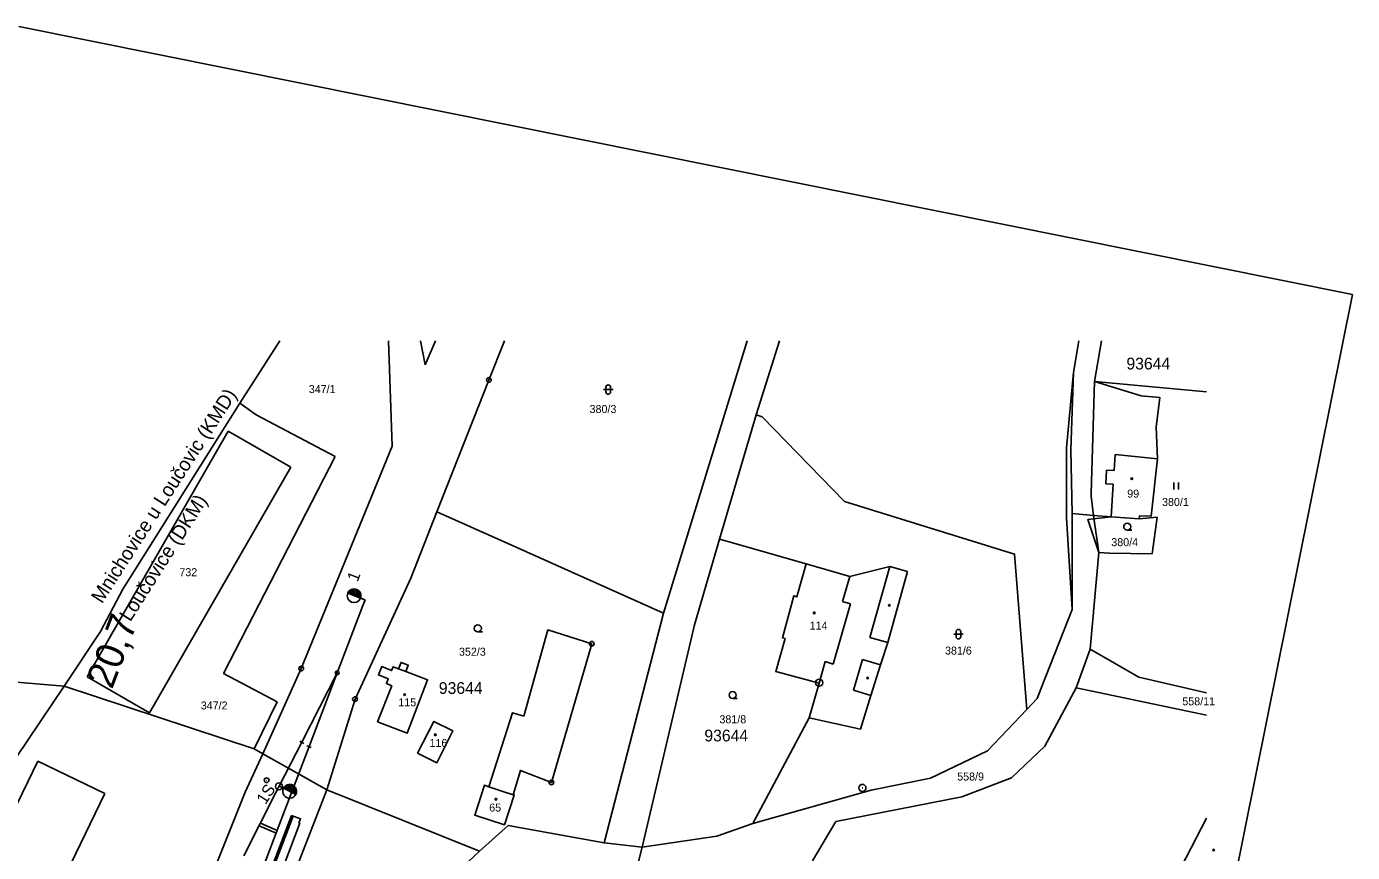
# Model space of a CAD drawing. Extents: x -778045 to -777594, y -1202682 to -1202213.
# Drawn here: x -777875.5 to -777593.8, y -1202388.9 to -1202213.3 of the extents above; entities that cross this region are included whole.
import ezdxf

# ---------------------------------------------------------------- set-up
doc = ezdxf.new("R2010")
doc.units = 0
for name, color, linetype in [('BPEJ', 7, 'Continuous'), ('GD_Starý stav', 7, 'Continuous'), ('Katastr_HRANICE DRÁHY', 7, 'Continuous'), ('Katastr_Hranice katastrální', 7, 'Continuous'), ('Katastr_Hranice parcel', 7, 'Continuous'), ('Katastr_Parcelní čísla', 7, 'Continuous'), ('Katastr_Slučkované čáry', 7, 'Continuous'), ('Katastr_Značky kultur', 7, 'Continuous'), ('Vrstva 7', 7, 'Continuous')]:
    doc.layers.add(name, color=color, linetype=linetype)

msp = doc.modelspace()

# ---------------------------------------------------------------- linework, layer by layer
at = {"layer": 'BPEJ'}
for points in [[(-777715.51, -1202280.12), (-777720.45, -1202295.86), (-777719.2, -1202296.33), (-777701.71, -1202314.27), (-777665.58, -1202325.46), (-777663.01, -1202358.54), (-777660.78, -1202356.18), (-777659.91, -1202353.96), (-777653.34, -1202337.23), (-777654.57, -1202317.8), (-777654.55, -1202302.89), (-777653.05, -1202286.88), (-777651.96, -1202280.12)], [(-777647.08, -1202280.12), (-777648.6, -1202288.78), (-777638.72, -1202291.84), (-777634.69, -1202292.2), (-777635.48, -1202298.47), (-777635.2, -1202305.22), (-777636.54, -1202317.41), (-777639.06, -1202317.35), (-777639.1, -1202318), (-777645.06, -1202317.53), (-777650.01, -1202318.12), (-777647.71, -1202325.12), (-777649.49, -1202345.7), (-777639.21, -1202351.67), (-777624.79, -1202354.99)], [(-777788.3, -1202316.49), (-777774.01, -1202322.88), (-777740.14, -1202338.03), (-777752.8, -1202386.89), (-777773.14, -1202383.15), (-777779.27, -1202388.61), (-777811.7, -1202375.6), (-777805.7, -1202356.3), (-777793.87, -1202330.63), (-777788.3, -1202316.49)], [(-777728.24, -1202322.3), (-777726.98, -1202322.66), (-777709.85, -1202327.57), (-777711.82, -1202334.53), (-777712.49, -1202334.34), (-777714.9, -1202343.3), (-777714.35, -1202343.45), (-777716.32, -1202350.41), (-777707.07, -1202352.95), (-777709.23, -1202360.29), (-777721.22, -1202382.72), (-777728.85, -1202385.43), (-777744.73, -1202387.77), (-777733.6, -1202340.49), (-777728.24, -1202322.3)], [(-777769.85, -1202359.94), (-777764.72, -1202341.59), (-777755.42, -1202344.55), (-777763.99, -1202374), (-777770.53, -1202371.45), (-777772.08, -1202376.64), (-777771.88, -1202376.7), (-777773.95, -1202383.02), (-777780.27, -1202380.95), (-777778.2, -1202374.63), (-777777.29, -1202374.93), (-777772.26, -1202359.22), (-777769.85, -1202359.94)], [(-777796.44, -1202349.87), (-777795.91, -1202348.51), (-777794.39, -1202349.09), (-777794.91, -1202350.46), (-777790.27, -1202352.24), (-777794.6, -1202363.54), (-777800.91, -1202361.12), (-777797.88, -1202353.49), (-777799.04, -1202353.02), (-777798.64, -1202352), (-777800.73, -1202351.17), (-777800.03, -1202349.39), (-777797.93, -1202350.23), (-777797.61, -1202349.41), (-777796.44, -1202349.87)], [(-777792.39, -1202367.77), (-777788.94, -1202361.03), (-777784.91, -1202363.08), (-777788.31, -1202369.84), (-777792.39, -1202367.77)]]:
    msp.add_lwpolyline(points, dxfattribs=at)
at = {"layer": 'Defpoints'}
for q in [(-777877.12, -1202213.32), (-777676.59, -1202682.05)]:
    msp.add_line((-777593.79, -1202270.29), q, dxfattribs=at)
at = {"layer": 'GD_Starý stav'}
for p, q in [((-777806.9, -1202333.95), (-777807.1, -1202333.51)), ((-777806.41, -1202334.14), (-777806.82, -1202333.21)), ((-777805.91, -1202334.33), (-777806.5, -1202333.01)), ((-777805.41, -1202334.52), (-777806.14, -1202332.9)), ((-777804.92, -1202334.71), (-777805.74, -1202332.88)), ((-777804.49, -1202334.75), (-777805.26, -1202333.02)), ((-777804.52, -1202334.86), (-777803.56, -1202335.22)), ((-777809.48, -1202350.75), (-777816.98, -1202365.49)), ((-777816.98, -1202365.49), (-777809.48, -1202350.75)), ((-777816.54, -1202365.72), (-777817.42, -1202365.26)), ((-777816.98, -1202365.49), (-777821.8, -1202374.78)), ((-777814.99, -1202366.59), (-777815.92, -1202366.23)), ((-777822.51, -1202376.18), (-777829.29, -1202389.61)), ((-777822.51, -1202376.18), (-777829.29, -1202389.61)), ((-777821.8, -1202374.78), (-777822.51, -1202376.18)), ((-777821.8, -1202374.78), (-777822.51, -1202376.18)), ((-777820.87, -1202375.24), (-777821.8, -1202374.78)), ((-777820.66, -1202374.94), (-777820.5, -1202375.43)), ((-777820.35, -1202374.67), (-777820.02, -1202375.67)), ((-777820, -1202374.51), (-777819.54, -1202375.92)), ((-777819.63, -1202374.44), (-777819.06, -1202376.16)), ((-777819.21, -1202374.48), (-777818.58, -1202376.4)), ((-777818.74, -1202374.69), (-777818.18, -1202376.37)), ((-777826.07, -1202383.23), (-777822.47, -1202384.82)), ((-777825.8, -1202382.7), (-777822.26, -1202384.26))]:
    msp.add_line(p, q, dxfattribs=at)
for points in [[(-777804.52, -1202334.86), (-777807.26, -1202333.81)], [(-777803.56, -1202335.22), (-777804.09, -1202336.62), (-777809.48, -1202350.75), (-777815.46, -1202366.41)], [(-777815.46, -1202366.41), (-777809.48, -1202350.75), (-777804.09, -1202336.62), (-777803.56, -1202335.22)], [(-777804.52, -1202334.86), (-777804.52, -1202334.86)], [(-777865.08, -1202504.23), (-777861.67, -1202489.74), (-777857.48, -1202477.13), (-777850.38, -1202458.32), (-777840.49, -1202432.25), (-777830.62, -1202406.28), (-777821.88, -1202383.27), (-777815.46, -1202366.41)], [(-777818.26, -1202376.56), (-777820.87, -1202375.24)], [(-777818.26, -1202376.56), (-777818.26, -1202376.56)], [(-777844.11, -1202457.24), (-777847.57, -1202455.83), (-777842.63, -1202442.78), (-777837.65, -1202429.62), (-777832.66, -1202416.55), (-777826.6, -1202400.65), (-777819.16, -1202381.05)], [(-777847.25, -1202456.03), (-777842.26, -1202442.89), (-777837.28, -1202429.79), (-777832.33, -1202416.64), (-777826.31, -1202400.77), (-777818.81, -1202381.19), (-777818.81, -1202381.2)], [(-777844.11, -1202457.24), (-777839.11, -1202444.1), (-777835.76, -1202435.24), (-777834.05, -1202430.85), (-777833.28, -1202428.8), (-777831.86, -1202428.99), (-777831.3, -1202427.43), (-777832.54, -1202426.83), (-777830.84, -1202422.31), (-777831.43, -1202422.03), (-777830.16, -1202418.71), (-777829.52, -1202418.79), (-777826.31, -1202410.46), (-777827.69, -1202409.96), (-777827.2, -1202408.71), (-777825.88, -1202409.2), (-777823.46, -1202402.62), (-777824.77, -1202402.13), (-777817.44, -1202382.7), (-777817.6, -1202382.63), (-777817.25, -1202381.75), (-777819.16, -1202381.05)]]:
    msp.add_lwpolyline(points, dxfattribs=at)
for centre, radius in [((-777805.9, -1202334.33), 1.46), ((-777809.48, -1202350.75), 0.4)]:
    msp.add_circle(centre, radius, dxfattribs=at)
for centre, start, end in [((-777805.89, -1202334.34), 339.1309, 159.0918), ((-777819.57, -1202375.9), 153.2834, 333.7529), ((-777819.57, -1202375.9), 333.368, 153.3289)]:
    msp.add_arc(centre, 1.46, start, end, dxfattribs=at)
at = {"layer": 'Katastr_HRANICE DRÁHY'}
for points in [[(-777798.62, -1202280.12), (-777797.84, -1202302.55)], [(-777791.78, -1202280.12), (-777790.77, -1202285.22)], [(-777790.77, -1202285.22), (-777788.57, -1202280.12)], [(-777777.27, -1202288.47), (-777773.95, -1202280.12)], [(-777788.3, -1202316.49), (-777777.27, -1202288.47)], [(-777817.11, -1202349.82), (-777797.84, -1202302.55)], [(-777788.3, -1202316.49), (-777793.87, -1202330.63)], [(-777805.7, -1202356.3), (-777793.87, -1202330.63)], [(-777817.11, -1202349.82), (-777825.29, -1202367.91)], [(-777805.7, -1202356.3), (-777811.7, -1202375.6)], [(-777825.29, -1202367.91), (-777829.01, -1202376.12)], [(-777841.03, -1202405.98), (-777829.01, -1202376.12)], [(-777811.7, -1202375.6), (-777821.08, -1202399.82)]]:
    msp.add_lwpolyline(points, dxfattribs=at)
at = {"layer": 'Katastr_Hranice katastrální'}
for points in [[(-777830.2, -1202293.41), (-777821.68, -1202280.12)], [(-777854.99, -1202332.94), (-777830.2, -1202293.41)], [(-777859.77, -1202341.9), (-777854.99, -1202332.94)], [(-777867.47, -1202353.53), (-777859.77, -1202341.9)], [(-777906.41, -1202350.32), (-777867.47, -1202353.53)]]:
    msp.add_lwpolyline(points, dxfattribs=at)
at = {"layer": 'Katastr_Hranice parcel'}
msp.add_line((-777648.6, -1202288.78), (-777624.79, -1202291.01), dxfattribs=at)
for points in [[(-777722.39, -1202280.12), (-777740.14, -1202338.03)], [(-777715.51, -1202280.12), (-777720.45, -1202295.86)], [(-777653.05, -1202286.88), (-777651.96, -1202280.12)], [(-777648.6, -1202288.78), (-777647.08, -1202280.12)], [(-777653.05, -1202286.88), (-777653.66, -1202303.32)], [(-777648.6, -1202288.78), (-777649.33, -1202312.52)], [(-777648.6, -1202288.78), (-777638.72, -1202291.84)], [(-777638.72, -1202291.84), (-777634.69, -1202292.2)], [(-777830.2, -1202293.41), (-777826.67, -1202295.84)], [(-777634.69, -1202292.2), (-777635.48, -1202298.47)], [(-777826.67, -1202295.84), (-777809.94, -1202304.72)], [(-777728.24, -1202322.3), (-777720.45, -1202295.86)], [(-777720.45, -1202295.86), (-777719.2, -1202296.33)], [(-777701.71, -1202314.27), (-777719.2, -1202296.33)], [(-777832.67, -1202299.35), (-777862.62, -1202351.59)], [(-777819.32, -1202307.02), (-777832.67, -1202299.35)], [(-777635.48, -1202298.47), (-777635.2, -1202305.22)], [(-777653.66, -1202303.32), (-777653.34, -1202316.88)], [(-777809.94, -1202304.72), (-777833.64, -1202350.84)], [(-777635.2, -1202305.22), (-777636.54, -1202317.41)], [(-777849.34, -1202359.23), (-777819.32, -1202307.02)], [(-777665.58, -1202325.46), (-777701.71, -1202314.27)], [(-777649.33, -1202312.52), (-777649.34, -1202313.17), (-777648.79, -1202317.24)], [(-777788.3, -1202316.49), (-777774.01, -1202322.88)], [(-777653.34, -1202316.88), (-777653.34, -1202337.23)], [(-777653.34, -1202316.88), (-777648.79, -1202317.24)], [(-777648.79, -1202317.24), (-777645.06, -1202317.53)], [(-777648.79, -1202317.24), (-777647.71, -1202325.12)], [(-777639.06, -1202317.35), (-777639.1, -1202318)], [(-777636.54, -1202317.41), (-777639.06, -1202317.35)], [(-777645.06, -1202317.53), (-777639.1, -1202318)], [(-777639.1, -1202318), (-777635.26, -1202317.6)], [(-777635.26, -1202317.6), (-777636.36, -1202325.39)], [(-777774.01, -1202322.88), (-777740.14, -1202338.03)], [(-777733.6, -1202340.49), (-777728.24, -1202322.3)], [(-777728.24, -1202322.3), (-777726.98, -1202322.66)], [(-777726.98, -1202322.66), (-777709.85, -1202327.57)], [(-777665.58, -1202325.46), (-777663.01, -1202358.54)], [(-777647.71, -1202325.12), (-777649.49, -1202345.7)], [(-777645.43, -1202325.29), (-777647.71, -1202325.12)], [(-777636.36, -1202325.39), (-777645.43, -1202325.29)], [(-777709.85, -1202327.57), (-777711.82, -1202334.53)], [(-777700.6, -1202330.22), (-777709.85, -1202327.57)], [(-777700.6, -1202330.22), (-777692.1, -1202328.08)], [(-777692.1, -1202328.08), (-777688.3, -1202329.15)], [(-777688.3, -1202329.15), (-777692.54, -1202344.26)], [(-777712.49, -1202334.34), (-777714.9, -1202343.3)], [(-777711.82, -1202334.53), (-777712.49, -1202334.34)], [(-777653.34, -1202337.23), (-777659.91, -1202353.96)], [(-777752.8, -1202386.89), (-777740.14, -1202338.03)], [(-777769.85, -1202359.94), (-777764.72, -1202341.59)], [(-777755.42, -1202344.55), (-777764.72, -1202341.59)], [(-777733.6, -1202340.49), (-777744.73, -1202387.77)], [(-777755.42, -1202344.55), (-777763.99, -1202374)], [(-777714.35, -1202343.45), (-777716.32, -1202350.41)], [(-777714.9, -1202343.3), (-777714.35, -1202343.45)], [(-777694.06, -1202349.02), (-777692.54, -1202344.26)], [(-777649.49, -1202345.7), (-777652.48, -1202353.91)], [(-777649.49, -1202345.7), (-777639.21, -1202351.67)], [(-777833.64, -1202350.84), (-777822.24, -1202356.89)], [(-777800.03, -1202349.39), (-777800.73, -1202351.17)], [(-777800.73, -1202351.17), (-777798.64, -1202352)], [(-777797.93, -1202350.23), (-777800.03, -1202349.39)], [(-777797.61, -1202349.41), (-777797.93, -1202350.23)], [(-777796.44, -1202349.87), (-777797.61, -1202349.41)], [(-777795.91, -1202348.51), (-777796.44, -1202349.87)], [(-777794.39, -1202349.09), (-777795.91, -1202348.51)], [(-777794.91, -1202350.46), (-777794.39, -1202349.09)], [(-777790.27, -1202352.24), (-777794.91, -1202350.46)], [(-777716.32, -1202350.41), (-777707.07, -1202352.95)], [(-777694.06, -1202349.02), (-777696.1, -1202355.56)], [(-777867.47, -1202353.53), (-777910.71, -1202417.71)], [(-777827.09, -1202366.89), (-777867.47, -1202353.53)], [(-777862.62, -1202351.59), (-777849.34, -1202359.23)], [(-777797.88, -1202353.49), (-777800.91, -1202361.12)], [(-777798.64, -1202352), (-777799.04, -1202353.02)], [(-777799.04, -1202353.02), (-777797.88, -1202353.49)], [(-777794.6, -1202363.54), (-777790.27, -1202352.24)], [(-777709.23, -1202360.29), (-777707.07, -1202352.95)], [(-777659.91, -1202353.96), (-777660.78, -1202356.18)], [(-777659.17, -1202366.28), (-777652.48, -1202353.91)], [(-777652.48, -1202353.91), (-777647.75, -1202354.88)], [(-777639.21, -1202351.67), (-777624.79, -1202354.99)], [(-777822.24, -1202356.89), (-777827.09, -1202366.89)], [(-777696.1, -1202355.56), (-777698.31, -1202362.67)], [(-777660.78, -1202356.18), (-777663.01, -1202358.54)], [(-777647.75, -1202354.88), (-777624.79, -1202359.75)], [(-777777.29, -1202374.93), (-777772.26, -1202359.22)], [(-777769.85, -1202359.94), (-777772.26, -1202359.22)], [(-777663.01, -1202358.54), (-777671.31, -1202367.29)], [(-777794.6, -1202363.54), (-777800.91, -1202361.12)], [(-777792.39, -1202367.77), (-777788.94, -1202361.03)], [(-777788.94, -1202361.03), (-777784.91, -1202363.08)], [(-777709.23, -1202360.29), (-777721.22, -1202382.72)], [(-777698.31, -1202362.67), (-777709.23, -1202360.29)], [(-777784.91, -1202363.08), (-777788.31, -1202369.84)], [(-777825.29, -1202367.91), (-777827.09, -1202366.89)], [(-777825.29, -1202367.91), (-777817.69, -1202372.21)], [(-777788.31, -1202369.84), (-777792.39, -1202367.77)], [(-777671.31, -1202367.29), (-777683.45, -1202373.1)], [(-777666.24, -1202373.06), (-777659.17, -1202366.28)], [(-777873.08, -1202369.51), (-777896.85, -1202418.53)], [(-777858.82, -1202376.38), (-777873.08, -1202369.51)], [(-777817.69, -1202372.21), (-777811.7, -1202375.6)], [(-777770.53, -1202371.45), (-777772.08, -1202376.64)], [(-777770.53, -1202371.45), (-777763.99, -1202374)], [(-777696.04, -1202375.65), (-777683.45, -1202373.1)], [(-777676.8, -1202377.11), (-777666.24, -1202373.06)], [(-777882.63, -1202425.49), (-777858.82, -1202376.38)], [(-777811.7, -1202375.6), (-777779.27, -1202388.61)], [(-777780.27, -1202380.95), (-777778.2, -1202374.63)], [(-777778.2, -1202374.63), (-777777.29, -1202374.93)], [(-777772.08, -1202376.64), (-777771.88, -1202376.7)], [(-777721.22, -1202382.72), (-777696.04, -1202375.65)], [(-777771.88, -1202376.7), (-777773.95, -1202383.02)], [(-777703.53, -1202382.3), (-777676.8, -1202377.11)], [(-777773.95, -1202383.02), (-777780.27, -1202380.95)], [(-777708.49, -1202390.66), (-777703.53, -1202382.3)], [(-777632.44, -1202396.39), (-777624.79, -1202381.58)], [(-777773.14, -1202383.15), (-777779.27, -1202388.61)], [(-777752.8, -1202386.89), (-777773.14, -1202383.15)], [(-777721.22, -1202382.72), (-777728.85, -1202385.43)], [(-777752.8, -1202386.89), (-777744.73, -1202387.77)], [(-777746.67, -1202395.6), (-777744.73, -1202387.77)], [(-777744.73, -1202387.77), (-777728.85, -1202385.43)], [(-777779.27, -1202388.61), (-777787.77, -1202396.63)]]:
    msp.add_lwpolyline(points, dxfattribs=at)
at = {"layer": 'Katastr_Slučkované čáry'}
for points in [[(-777644.45, -1202307.69), (-777644.24, -1202304.29)], [(-777644.24, -1202304.29), (-777635.2, -1202305.22)], [(-777646.22, -1202310.52), (-777646.07, -1202307.64)], [(-777646.07, -1202307.64), (-777644.45, -1202307.69)], [(-777644.63, -1202310.61), (-777646.22, -1202310.52)], [(-777645.06, -1202317.53), (-777644.63, -1202310.61)], [(-777692.1, -1202328.08), (-777696.34, -1202343.19)], [(-777702.13, -1202335.55), (-777700.6, -1202330.22)], [(-777704.14, -1202348.88), (-777700.46, -1202336.06)], [(-777700.46, -1202336.06), (-777702.13, -1202335.55)], [(-777696.34, -1202343.19), (-777692.54, -1202344.26)], [(-777707.07, -1202352.95), (-777705.8, -1202348.34)], [(-777705.8, -1202348.34), (-777704.14, -1202348.88)], [(-777697.89, -1202347.88), (-777699.83, -1202354.38)], [(-777694.06, -1202349.02), (-777697.89, -1202347.88)], [(-777796.44, -1202349.87), (-777794.91, -1202350.46)], [(-777699.83, -1202354.38), (-777696.1, -1202355.56)], [(-777777.29, -1202374.93), (-777774.48, -1202375.85)], [(-777772.08, -1202376.64), (-777774.48, -1202375.85)]]:
    msp.add_lwpolyline(points, dxfattribs=at)
at = {"layer": 'Katastr_Značky kultur'}
for p, q in [((-777777.32, -1202288.47), (-777777.22, -1202288.47)), ((-777752.89, -1202290.51), (-777750.89, -1202290.51)), ((-777752.39, -1202290.01), (-777752.39, -1202291.01)), ((-777751.39, -1202290.01), (-777751.39, -1202291.01)), ((-777631.73, -1202310.25), (-777631.73, -1202311.75)), ((-777630.73, -1202311.75), (-777630.73, -1202310.25)), ((-777641.65, -1202320.41), (-777640.65, -1202320.41)), ((-777779.61, -1202342.01), (-777778.61, -1202342.01)), ((-777678.51, -1202342.5), (-777676.51, -1202342.5)), ((-777678.01, -1202342), (-777678.01, -1202343)), ((-777677.01, -1202342), (-777677.01, -1202343)), ((-777755.47, -1202344.55), (-777755.37, -1202344.55)), ((-777817.16, -1202349.82), (-777817.06, -1202349.82)), ((-777707.14, -1202352.82), (-777707.04, -1202352.82)), ((-777805.75, -1202356.3), (-777805.65, -1202356.3)), ((-777725.48, -1202356.19), (-777724.48, -1202356.19)), ((-777764.04, -1202374), (-777763.94, -1202374)), ((-777697.95, -1202375.18), (-777697.85, -1202375.18))]:
    msp.add_line(p, q, dxfattribs=at)
for centre, radius in [((-777777.27, -1202288.47), 0.499), ((-777640.68, -1202309.44), 0.175), ((-777641.65, -1202319.66), 0.75), ((-777692.19, -1202336.36), 0.175), ((-777708.15, -1202337.98), 0.175), ((-777779.61, -1202341.26), 0.75), ((-777755.42, -1202344.55), 0.499), ((-777817.11, -1202349.82), 0.499), ((-777707.09, -1202352.82), 0.756), ((-777696.79, -1202351.8), 0.175), ((-777805.7, -1202356.3), 0.499), ((-777795.14, -1202355.37), 0.175), ((-777725.48, -1202355.44), 0.75), ((-777788.62, -1202363.89), 0.175), ((-777763.99, -1202374), 0.499), ((-777697.9, -1202375.18), 0.756), ((-777775.78, -1202377.59), 0.175), ((-777623.28, -1202388.38), 0.175)]:
    msp.add_circle(centre, radius, dxfattribs=at)
for centre, start, end in [((-777751.89, -1202290.01), 0, 180), ((-777751.89, -1202291.01), 180, 0), ((-777677.51, -1202342), 0, 180), ((-777677.51, -1202343), 180, 0)]:
    msp.add_arc(centre, 0.5, start, end, dxfattribs=at)
at = {"layer": 'Vrstva 7'}
msp.add_line((-777824.44, -1202373.51), (-777824.49, -1202373.59), dxfattribs=at)
for centre, radius in [((-777824.47, -1202373.55), 0.5), ((-777821.85, -1202374.86), 0.75)]:
    msp.add_circle(centre, radius, dxfattribs=at)

# ---------------------------------------------------------------- texts
at = {"layer": 'BPEJ'}
for p in [(-777641.82, -1202286.23), (-777787.89, -1202355.2), (-777731.48, -1202365.3)]:
    msp.add_text('93644', height=2.5, dxfattribs=at).set_placement(p)
at = {"layer": 'GD_Starý stav'}
for s, rotation, p in [('1', 69.1114, (-777805.14, -1202331.51)), ('1S', 57.2611, (-777824.71, -1202378.86))]:
    msp.add_text(s, height=2.5, rotation=rotation, dxfattribs=at).set_placement(p)
at = {"layer": 'Katastr_Hranice katastrální'}
for s, rotation, p in [('Mnichovice u Loučovic (KMD)', 57.21, (-777859.45, -1202336.17)), ('Loučovice (DKM)', 57.5887, (-777853.45, -1202340.02))]:
    msp.add_text(s, height=3, rotation=rotation, dxfattribs=at).set_placement(p)
at = {"layer": 'Katastr_Parcelní čísla'}
for s, p in [('347/1', (-777815.52, -1202291.25)), ('380/3', (-777755.87, -1202295.49)), ('99', (-777641.65, -1202313.47)), ('380/1', (-777634.25, -1202315.25)), ('380/4', (-777645.03, -1202323.79)), ('732', (-777843.01, -1202330.17)), ('114', (-777709.13, -1202341.52)), ('352/3', (-777783.61, -1202347.08)), ('381/6', (-777680.36, -1202346.84)), ('347/2', (-777838.47, -1202358.51)), ('115', (-777796.5, -1202357.84)), ('558/11', (-777629.94, -1202357.62)), ('381/8', (-777728.28, -1202361.44)), ('116', (-777789.88, -1202366.48)), ('558/9', (-777677.77, -1202373.61)), ('65', (-777777.19, -1202380.22))]:
    msp.add_text(s, height=1.7, dxfattribs=at).set_placement(p)
at = {"layer": 'Vrstva 7'}
msp.add_text('20,7', height=6, rotation=69.1195, dxfattribs=at).set_placement((-777857.32, -1202354.38))

doc.saveas('drawing.dxf')
